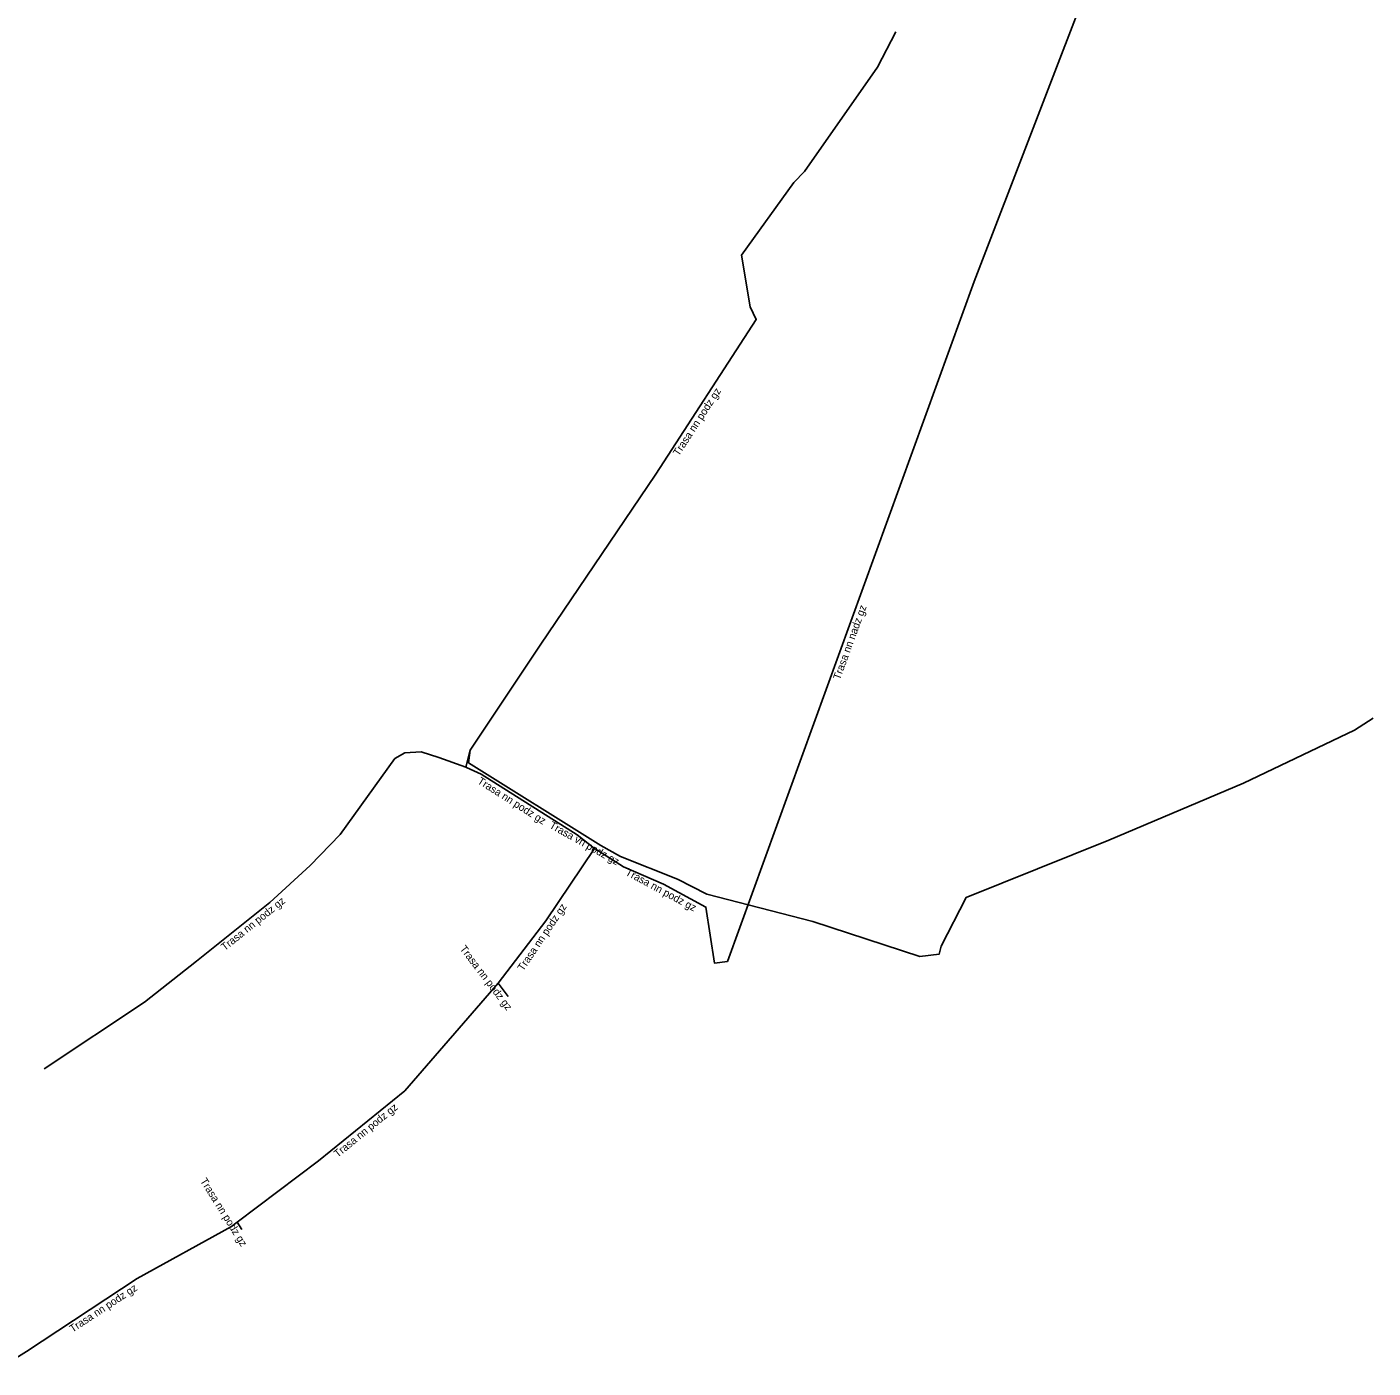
# Model space of a CAD drawing. Extents: x -682361 to -681785, y -994505 to -993892.
# Drawn here: x -682250 to -682161.3, y -994433.6 to -994345.2 of the extents above; entities that cross this region are included whole.
import ezdxf

# ---------------------------------------------------------------- set-up
doc = ezdxf.new("R2010")
doc.units = 0
for name, color, linetype in [('Popiskový text - Ostatní atributy Trasy', 7, 'Continuous'), ('Spojnice NN', 7, 'Continuous'), ('Spojnice VN', 7, 'Continuous')]:
    doc.layers.add(name, color=color, linetype=linetype)

msp = doc.modelspace()

# ---------------------------------------------------------------- linework, layer by layer
at = {"layer": 'Spojnice NN'}
for points in [[(-682171.63, -994320.42), (-682187.61, -994361.991)], [(-682221.082, -994394.001), (-682220.799, -994392.881), (-682216.191, -994385.95), (-682208.583, -994374.685), (-682201.963, -994364.493), (-682202.361, -994363.676), (-682202.924, -994360.262), (-682199.479, -994355.486), (-682198.794, -994354.756), (-682193.967, -994347.868), (-682192.77, -994345.54)], [(-682203.85, -994406.8), (-682187.61, -994361.991)], [(-682248.849, -994413.867), (-682242.238, -994409.475), (-682238.826, -994406.78), (-682234.005, -994402.918), (-682231.345, -994400.47), (-682229.358, -994398.437), (-682225.767, -994393.427), (-682225.109, -994393.046), (-682224.035, -994392.975), (-682222.875, -994393.355), (-682221.082, -994394.001), (-682221.039, -994394.02)], [(-682221.039, -994394.02), (-682220.068, -994394.451), (-682213.758, -994398.464), (-682212.605, -994399.348), (-682212.576, -994399.367)], [(-682218.967, -994408.235), (-682215.823, -994404.111), (-682212.605, -994399.348)], [(-682212.576, -994399.367), (-682210.704, -994400.553), (-682208.079, -994401.7), (-682205.271, -994403.211), (-682204.712, -994406.907), (-682203.85, -994406.8)], [(-682236.142, -994423.971), (-682230.783, -994419.922), (-682225.111, -994415.311), (-682218.967, -994408.235)], [(-682218.967, -994408.235), (-682218.302, -994409.106)], [(-682251.807, -994433.585), (-682250.016, -994432.482), (-682242.728, -994427.677), (-682236.519, -994424.256), (-682236.142, -994423.971)], [(-682236.142, -994423.971), (-682235.838, -994424.459)]]:
    msp.add_lwpolyline(points, dxfattribs=at)
at = {"layer": 'Spojnice VN'}
msp.add_lwpolyline([(-682161.34, -994390.76), (-682162.554, -994391.558), (-682169.87, -994395.04), (-682178.731, -994398.81), (-682188.144, -994402.572), (-682189.779, -994405.791), (-682189.915, -994406.315), (-682191.18, -994406.476), (-682198.233, -994404.172), (-682205.22, -994402.359), (-682207.149, -994401.37), (-682210.894, -994399.877), (-682212.186, -994399.154), (-682220.915, -994393.702), (-682220.799, -994392.881), (-682216.191, -994385.95), (-682208.583, -994374.685), (-682201.963, -994364.493), (-682202.361, -994363.676), (-682202.924, -994360.262), (-682199.479, -994355.486), (-682198.794, -994354.756)], dxfattribs=at)

# ---------------------------------------------------------------- texts
at = {"layer": 'Popiskový text - Ostatní atributy Trasy'}
for s, rotation, p in [('Trasa nn podz gz', 56.99511, (-682207.062, -994373.538)), ('Trasa nn nadz gz', 70.07811, (-682196.446, -994388.278)), ('Trasa nn podz gz', 327.54467, (-682220.368, -994395.03)), ('Trasa vn podz gz', 330.76873, (-682215.632, -994397.971)), ('Trasa nn podz gz', 331.71506, (-682210.62, -994401.07)), ('Trasa nn podz gz', 38.69747, (-682236.962, -994406.119)), ('Trasa nn podz gz', 55.95607, (-682217.307, -994407.468)), ('Trasa nn podz gz', 307.36138, (-682221.514, -994405.97)), ('Trasa nn podz gz', 39.10907, (-682229.529, -994419.74)), ('Trasa nn podz gz', 301.92088, (-682238.601, -994421.253)), ('Trasa nn podz gz', 33.39698, (-682246.986, -994431.263))]:
    msp.add_text(s, height=0.5, rotation=rotation, dxfattribs=at).set_placement(p)

doc.saveas('drawing.dxf')
